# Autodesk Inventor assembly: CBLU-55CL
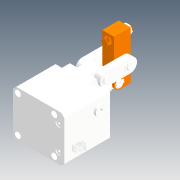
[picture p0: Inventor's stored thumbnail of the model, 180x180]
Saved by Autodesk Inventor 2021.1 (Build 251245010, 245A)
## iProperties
Created: 2019-05
Part Number: CBLU-55CL
Description: STEP AP214
Document SubType Name: Assembly
Designer: user
Title: CBLU-55CL.STEP
Revision Number: ÈÎºÎ
Sending System: SolidWorks 2016
Preprocessor: SwSTEP 2.0
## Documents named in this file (13)
- D:\Vault_2016\Projekty\Clamptek\Hydraulic\CBLU\CBLU-55\Inventor\CBLU-55CL\CBLU-55CL.iam
- D:\Vault_2016\Projekty\Clamptek\Hydraulic\CBLU\CBLU-55\Inventor\CBLU-55CL\CBLU-55CL±¾Ìå_1_2.ipt
- D:\Vault_2016\Projekty\Clamptek\Hydraulic\CBLU\CBLU-55\Inventor\CBLU-55CL\changxiao.ipt
- D:\Vault_2016\Projekty\Clamptek\Hydraulic\CBLU\CBLU-55\Inventor\CBLU-55CL\duanxiao.ipt
- D:\Vault_2016\Projekty\Clamptek\Hydraulic\CBLU\CBLU-55\Inventor\CBLU-55CL\huosaigan_1_1.ipt
- D:\Vault_2016\Projekty\Clamptek\Hydraulic\CBLU\CBLU-55\Inventor\CBLU-55CL\kahuang.ipt
- D:\Vault_2016\Projekty\Clamptek\Hydraulic\CBLU\CBLU-55\Inventor\CBLU-55CL\kahuang01.ipt
- D:\Vault_2016\Projekty\Clamptek\Hydraulic\CBLU\CBLU-55\Inventor\CBLU-55CL\liangan.ipt
- D:\Vault_2016\Projekty\Clamptek\Hydraulic\CBLU\CBLU-55\Inventor\CBLU-55CL\luogan.ipt
- D:\Vault_2016\Projekty\Clamptek\Hydraulic\CBLU\CBLU-55\Inventor\CBLU-55CL\luomu.ipt
- D:\Vault_2016\Projekty\Clamptek\Hydraulic\CBLU\CBLU-55\Inventor\CBLU-55CL\yabi.ipt
- D:\Vault_2016\Projekty\Clamptek\Hydraulic\CBLU\CBLU-55\Inventor\CBLU-55CL\CZL20µ÷ËÙ·§_1_2.ipt
- D:\Vault_2016\Projekty\Clamptek\Hydraulic\CBLU\CBLU-55\Inventor\CBLU-55CL\ÄÚÁù½Ç¶ÂÍ·×îÐÂ1-4_1.ipt
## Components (18 placed, 18 different names)
1. CBLU-55CL±¾Ìå_1_2_1
2. changxiao_2
3. duanxiao_3
4. huosaigan_1_1_4
5. kahuang_5
6. kahuang01_6
7. liangan_7
8. luogan_8
9. luomu_9
10. yabi_10
11. liangan_11
12. kahuang01_12
13. changxiao_13
14. kahuang_14
15. kahuang_15
16. kahuang_16
17. CZL20µ÷ËÙ·§_1_2_17
18. ÄÚÁù½Ç¶ÂÍ·×îÐÂ1-4_1_18
